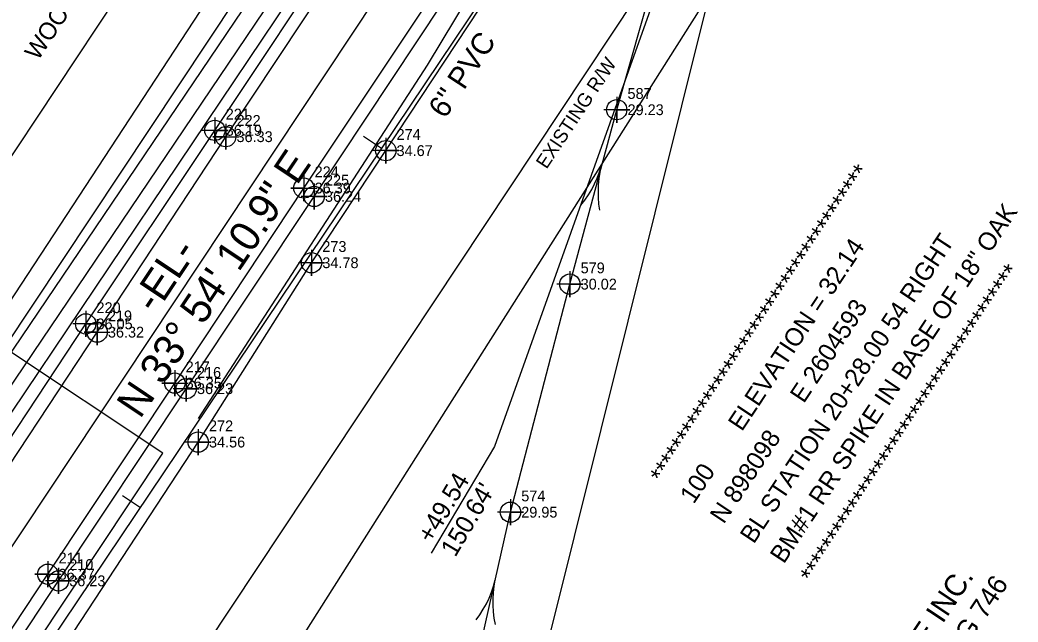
# Model space of a CAD drawing. Extents: x 2603627 to 2605187, y 896619 to 899063.
# Drawn here: x 2604393.2 to 2604624, y 897913.7 to 898052.8 of the extents above; entities that cross this region are included whole.
import ezdxf

# ---------------------------------------------------------------- set-up
doc = ezdxf.new("R2010")
doc.units = 0
for name, color, linetype in [('CTL Sheet Text', 7, 'Continuous'), ('Exist DTM Drainline Cogo Elevation', 7, 'Continuous'), ('Exist DTM Drainline Cogo Number', 7, 'Continuous'), ('Exist DTM Drainline Cogo Point CELL', 7, 'Continuous'), ('Exist Guardrail', 7, 'Continuous'), ('Exist Horizontal Alignment', 7, 'Continuous'), ('Exist Horizontal Alignment Direction Label', 7, 'Continuous'), ('Exist Horizontal Baseline Alignment', 7, 'Continuous'), ('Exist Horizontal Baseline Alignment Direction Label', 7, 'Continuous'), ('Exist Horizontal Baseline Alignment Tick small', 7, 'Continuous'), ('Exist Hydro Jurisdictional Stream or Body of Water', 7, 'Continuous'), ('Exist Hydro Stream Flow Arrow CELL', 7, 'Continuous'), ('Exist Property Deed Book Text', 7, 'Continuous'), ('Exist Property Line', 7, 'Continuous'), ('Exist Property Owner Text', 7, 'Continuous'), ('Exist Property Tie Line Leader', 7, 'Continuous'), ('Exist Property Tie Line Text', 7, 'Continuous'), ('Exist Right of Way Line', 7, 'Continuous'), ('Exist Right of Way Line Text', 7, 'Continuous'), ('Exist Roads EOP', 7, 'Continuous'), ('Exist Roads EOP Cogo Elevation', 7, 'Continuous'), ('Exist Roads EOP Cogo Number', 7, 'Continuous'), ('Exist Roads EOP Cogo Point CELL', 7, 'Continuous'), ('Exist Roads EOT', 7, 'Continuous'), ('Exist Roads EOT Cogo Elevation', 7, 'Continuous'), ('Exist Roads EOT Cogo Number', 7, 'Continuous'), ('Exist Roads EOT Cogo Point CELL', 7, 'Continuous'), ('Exist Utilities Telephone UG Cable SUE LOS C', 7, 'Continuous'), ('Exist Utilities Telephone UG FO SUE LOS C', 7, 'Continuous'), ('Exist Utilities Water UG Line SUE LOS B', 7, 'Continuous'), ('Exist Utilities Water UG Line SUE LOS B Cogo Elevation', 7, 'Continuous'), ('Exist Utilities Water UG Line SUE LOS B Cogo Number', 7, 'Continuous'), ('Exist Utilities Water UG Line SUE LOS B Cogo Point CELL', 7, 'Continuous'), ('Exist Utilities Water UG Line SUE LOS B Text', 7, 'Continuous'), ('Exist Vegetation Woods Line', 7, 'Continuous'), ('Exist Vegetation Woods Line Text', 7, 'Continuous')]:
    doc.layers.add(name, color=color, linetype=linetype)

# ---------------------------------------------------------------- blocks, each defined once
blk = doc.blocks.new('EXIST ROADS EOP COGO POINT')
at = {"layer": 'Exist Roads EOP Cogo Point CELL'}
blk.add_lwpolyline([(0, 0.06), (0, -0.06), (0, 0), (0.06, 0), (-0.06, 0)], dxfattribs=at)
blk.add_circle((0, 0), 0.0469, dxfattribs=at)
blk = doc.blocks.new('EXIST ROADS EOT COGO POINT')
at = {"layer": 'Exist Roads EOT Cogo Point CELL'}
blk.add_lwpolyline([(0, 0.06), (0, -0.06), (0, 0), (-0.06, 0), (0.06, 0)], dxfattribs=at)
blk.add_circle((0, 0), 0.0469, dxfattribs=at)
blk = doc.blocks.new('EXIST UTILITIES WATER UG LINE SUE LOS B COGO POINT')
at = {"layer": 'Exist Utilities Water UG Line SUE LOS B Cogo Point CELL'}
blk.add_lwpolyline([(0, 0.06), (0, -0.06), (0, 0), (0.06, 0), (-0.06, 0)], dxfattribs=at)
blk.add_circle((0, 0), 0.0469, dxfattribs=at)
blk = doc.blocks.new('EXIST DTM DRAINLINE COGO POINT')
at = {"layer": 'Exist DTM Drainline Cogo Point CELL'}
blk.add_lwpolyline([(0, 0.06), (0, -0.06), (0, 0), (0.06, 0), (-0.06, 0)], dxfattribs=at)
blk.add_circle((0, 0), 0.0469, dxfattribs=at)

msp = doc.modelspace()

# ---------------------------------------------------------------- linework, layer by layer
at = {"layer": 'Exist Guardrail'}
msp.add_lwpolyline([(2604516.08, 898089.95), (2604487.4, 898042.34), (2604434.45, 897960.66)], dxfattribs=at)
at = {"layer": 'Exist Horizontal Alignment'}
msp.add_line((2604046.33, 897411.6), (2604501.12, 898096.36), dxfattribs=at)
at = {"layer": 'Exist Horizontal Baseline Alignment'}
msp.add_line((2604301.74, 897762.53), (2604544.96, 898124.44), dxfattribs=at)
at = {"layer": 'Exist Horizontal Baseline Alignment Tick small'}
for p, q in [((2604476.83, 898023.06), (2604472.68, 898025.85)), ((2604421.06, 897940.07), (2604416.91, 897942.85))]:
    msp.add_line(p, q, dxfattribs=at)
at = {"layer": 'Exist Hydro Jurisdictional Stream or Body of Water'}
msp.add_lwpolyline([(2604496.63, 897894.57), (2604506.62, 897939.05), (2604520.36, 897991.75), (2604531.2, 898032.05), (2604542.79, 898072.73), (2604553.75, 898102.57), (2604562.26, 898124.95)], dxfattribs=at)
at = {"layer": 'Exist Hydro Stream Flow Arrow CELL'}
for p, q in [((2604526.4, 898014.23), (2604526.4, 898014.23)), ((2604502.01, 897918.51), (2604502.01, 897918.51))]:
    msp.add_line(p, q, dxfattribs=at)
for points in [[(2604522.9, 898009.99), (2604523.82, 898011.13), (2604524.64, 898012.39), (2604525.43, 898013.64), (2604526.1, 898014.92), (2604526.71, 898016.27), (2604527.25, 898017.66), (2604527.7, 898019.06)], [(2604527.31, 898008.81), (2604527.08, 898010.25), (2604527.01, 898011.75), (2604526.95, 898013.23), (2604527.02, 898014.67), (2604527.17, 898016.15), (2604527.4, 898017.62), (2604527.7, 898019.06)], [(2604498.68, 897914.14), (2604499.56, 897915.31), (2604500.32, 897916.6), (2604501.06, 897917.88), (2604501.68, 897919.19), (2604502.23, 897920.57), (2604502.71, 897921.98), (2604503.11, 897923.39)], [(2604503.15, 897913.13), (2604502.85, 897914.57), (2604502.72, 897916.06), (2604502.6, 897917.54), (2604502.6, 897918.98), (2604502.69, 897920.46), (2604502.86, 897921.95), (2604503.11, 897923.39)]]:
    msp.add_lwpolyline(points, dxfattribs=at)
at = {"layer": 'Exist Property Line'}
msp.add_line((2604562.45, 898098.35), (2604410.23, 897487.88), dxfattribs=at)
at = {"layer": 'Exist Property Tie Line Leader'}
msp.add_lwpolyline([(2604573.79, 898143.82), (2604569.62, 898141.11), (2604502.96, 897954.22), (2604488.28, 897929.59)], dxfattribs=at)
at = {"layer": 'Exist Right of Way Line'}
for p, q in [((2604004.68, 897439.26), (2604459.47, 898124.02)), ((2604087.98, 897383.94), (2604542.77, 898068.69))]:
    msp.add_line(p, q, dxfattribs=at)
at = {"layer": 'Exist Roads EOP'}
for points in [[(2604034.94, 897419.16), (2604054.97, 897449.51), (2604085.58, 897495.18), (2604114.88, 897539.87), (2604143.93, 897583.57), (2604172.72, 897627.19), (2604201.64, 897670.62), (2604230.5, 897714.45), (2604261.1, 897760.21), (2604291.23, 897805.76), (2604320.82, 897850.24), (2604350.34, 897894.81), (2604379.01, 897938.02), (2604408.4, 897982.56), (2604438.29, 898027.28), (2604468.22, 898072.28), (2604496.92, 898115.7)], [(2604057.72, 897404.05), (2604078.22, 897434.83), (2604108.36, 897480.05), (2604137.93, 897524.86), (2604167.35, 897568.96), (2604196.06, 897612.17), (2604224.86, 897655.68), (2604253.51, 897698.95), (2604283.96, 897744.64), (2604314.74, 897791.03), (2604343.97, 897835.34), (2604373.31, 897879.6), (2604402.1, 897923.18), (2604431.64, 897967.59), (2604461.24, 898012.02), (2604491.05, 898056.88), (2604519.7, 898100.47)]]:
    msp.add_lwpolyline(points, dxfattribs=at)
at = {"layer": 'Exist Roads EOT'}
for points in [[(2604037.37, 897417.54), (2604057.46, 897447.93), (2604087.91, 897493.66), (2604117.35, 897538.28), (2604146.54, 897581.98), (2604175.28, 897625.51), (2604204.1, 897668.97), (2604233.05, 897712.63), (2604263.81, 897758.51), (2604293.89, 897804.07), (2604323.3, 897848.54), (2604352.86, 897893.08), (2604381.65, 897936.11), (2604411.04, 897980.65), (2604440.78, 898025.82), (2604470.61, 898070.74), (2604499.36, 898114.11)], [(2604055.13, 897405.77), (2604075.39, 897436.3), (2604105.72, 897481.84), (2604135.41, 897526.58), (2604164.51, 897570.47), (2604193.14, 897613.84), (2604222.02, 897657.58), (2604250.73, 897700.63), (2604281.08, 897746.07), (2604311.9, 897792.56), (2604341.37, 897836.94), (2604370.82, 897881.24), (2604399.64, 897924.71), (2604429.03, 897968.88), (2604458.85, 898013.95), (2604488.44, 898058.33), (2604517.14, 898101.52)]]:
    msp.add_lwpolyline(points, dxfattribs=at)
at = {"layer": 'Exist Utilities Telephone UG Cable SUE LOS C'}
for p, q in [((2604364.02, 897921.59), (2604492.57, 898112.76)), ((2604389.62, 897977.06), (2604474.1, 898104.18)), ((2604426.24, 897952.72), (2604389.62, 897977.06)), ((2604201.56, 897614.6), (2604426.24, 897952.72))]:
    msp.add_line(p, q, dxfattribs=at)
at = {"layer": 'Exist Utilities Telephone UG FO SUE LOS C'}
for p, q in [((2604020.98, 897428.41), (2604461.82, 898080.46)), ((2604024.53, 897426.06), (2604465.37, 898078.1))]:
    msp.add_line(p, q, dxfattribs=at)
at = {"layer": 'Exist Utilities Water UG Line SUE LOS B'}
msp.add_lwpolyline([(2604076.5, 897391.6), (2604089.19, 897412.44), (2604108.02, 897444.81), (2604130.46, 897486.17), (2604138.61, 897502.5), (2604141.74, 897510.42), (2604157.29, 897542.11), (2604195.61, 897598.86), (2604232.99, 897655.2), (2604269.72, 897709.19), (2604303.43, 897758.71), (2604343.24, 897819.02), (2604371.6, 897861.28), (2604402.52, 897906.63), (2604434.42, 897955.25), (2604460.63, 897996.69), (2604477.79, 898022.59), (2604502.25, 898059.64), (2604529.4, 898098.89), (2604530.47, 898100.43), (2604537.02, 898109.88), (2604550.55, 898129.28)], dxfattribs=at)
at = {"layer": 'Exist Vegetation Woods Line'}
for points in [[(2604476.15, 898117.83), (2604185.5, 897674.67)], [(2604278.2, 897626.01), (2604559.06, 898068.86)]]:
    msp.add_lwpolyline(points, dxfattribs=at)

# ---------------------------------------------------------------- block references
at = {"layer": 'Exist DTM Drainline Cogo Point CELL', "xscale": 50, "yscale": 50}
for p in [(2604531.2, 898032.05), (2604520.36, 897991.75), (2604506.62, 897939.05)]:
    msp.add_blockref('EXIST DTM DRAINLINE COGO POINT', p, dxfattribs=at)
at = {"layer": 'Exist Roads EOP Cogo Point CELL', "xscale": 50, "yscale": 50}
for p in [(2604438.29, 898027.28), (2604461.24, 898012.02), (2604408.4, 897982.56), (2604431.64, 897967.59), (2604402.1, 897923.18)]:
    msp.add_blockref('EXIST ROADS EOP COGO POINT', p, dxfattribs=at)
at = {"layer": 'Exist Roads EOT Cogo Point CELL', "xscale": 50, "yscale": 50}
for p in [(2604440.78, 898025.82), (2604458.85, 898013.95), (2604411.04, 897980.65), (2604429.03, 897968.88), (2604399.64, 897924.71)]:
    msp.add_blockref('EXIST ROADS EOT COGO POINT', p, dxfattribs=at)
at = {"layer": 'Exist Utilities Water UG Line SUE LOS B Cogo Point CELL', "xscale": 50, "yscale": 50}
for p in [(2604477.79, 898022.59), (2604460.63, 897996.69), (2604434.42, 897955.25)]:
    msp.add_blockref('EXIST UTILITIES WATER UG LINE SUE LOS B COGO POINT', p, dxfattribs=at)

# ---------------------------------------------------------------- texts
at = {"layer": 'CTL Sheet Text'}
for s, p in [('****************************************', (2604542.07, 897945.37)), ('BM#1 RR SPIKE IN BASE OF 18" OAK', (2604569.84, 897926.93)), ('BL STATION 20+28.00 54 RIGHT', (2604562.89, 897931.54)), ('100       ELEVATION = 32.14', (2604549.01, 897940.76)), ('****************************************', (2604576.78, 897922.32)), ('N 898098      E 2604593', (2604555.95, 897936.15))]:
    msp.add_text(s, height=4.1667, rotation=56.4094, dxfattribs=at).set_placement(p)
at = {"layer": 'Exist DTM Drainline Cogo Elevation'}
for s, p in [('29.23', (2604533.7, 898030.8)), ('30.02', (2604522.86, 897990.5)), ('29.95', (2604509.12, 897937.8))]:
    msp.add_text(s, height=2.5, dxfattribs=at).set_placement(p)
at = {"layer": 'Exist DTM Drainline Cogo Number'}
for s, p in [('587', (2604533.7, 898034.55)), ('579', (2604522.86, 897994.25)), ('574', (2604509.12, 897941.55))]:
    msp.add_text(s, height=2.5, dxfattribs=at).set_placement(p)
at = {"layer": 'Exist Horizontal Alignment Direction Label'}
msp.add_text('-EL-', height=7, rotation=56.4094, dxfattribs=at).set_placement((2604424.55, 897984.67))
at = {"layer": 'Exist Horizontal Baseline Alignment Direction Label'}
msp.add_text('N 33%%d 54\' 10.9" E', height=7, rotation=56.097, dxfattribs=at).set_placement((2604420.97, 897960.41))
at = {"layer": 'Exist Property Deed Book Text'}
msp.add_text('DB 642 PG 746', height=4.5, rotation=56.4133, dxfattribs=at).set_placement((2604598.6, 897887.36))
at = {"layer": 'Exist Property Owner Text'}
msp.add_text('ELE INC.', height=5, rotation=56.4133, dxfattribs=at).set_placement((2604598.54, 897901.04))
at = {"layer": 'Exist Property Tie Line Text'}
for s, p in [('+49.54', (2604488.41, 897931.64)), ("150.64'", (2604493.86, 897928.47))]:
    msp.add_text(s, height=4.2, rotation=59.1717, dxfattribs=at).set_placement(p)
at = {"layer": 'Exist Right of Way Line Text'}
msp.add_text('EXISTING R/W', height=3.2, rotation=56.4094, dxfattribs=at).set_placement((2604514.97, 898018.17))
at = {"layer": 'Exist Roads EOP Cogo Elevation'}
for s, p in [('36.19', (2604440.79, 898026.03)), ('36.24', (2604463.74, 898010.77)), ('36.05', (2604410.9, 897981.31)), ('36.23', (2604434.14, 897966.34)), ('36.23', (2604404.6, 897921.93))]:
    msp.add_text(s, height=2.5, dxfattribs=at).set_placement(p)
at = {"layer": 'Exist Roads EOP Cogo Number'}
for s, p in [('221', (2604440.79, 898029.78)), ('225', (2604463.74, 898014.52)), ('220', (2604410.9, 897985.06)), ('216', (2604434.14, 897970.09)), ('210', (2604404.6, 897925.68))]:
    msp.add_text(s, height=2.5, dxfattribs=at).set_placement(p)
at = {"layer": 'Exist Roads EOT Cogo Elevation'}
for s, p in [('36.33', (2604443.28, 898024.57)), ('36.39', (2604461.35, 898012.7)), ('36.32', (2604413.54, 897979.4)), ('36.35', (2604431.53, 897967.63)), ('36.37', (2604402.14, 897923.46))]:
    msp.add_text(s, height=2.5, dxfattribs=at).set_placement(p)
at = {"layer": 'Exist Roads EOT Cogo Number'}
for s, p in [('222', (2604443.28, 898028.32)), ('224', (2604461.35, 898016.45)), ('219', (2604413.54, 897983.15)), ('217', (2604431.53, 897971.38)), ('211', (2604402.14, 897927.21))]:
    msp.add_text(s, height=2.5, dxfattribs=at).set_placement(p)
at = {"layer": 'Exist Utilities Water UG Line SUE LOS B Cogo Elevation'}
for s, p in [('34.67', (2604480.29, 898021.34)), ('34.78', (2604463.13, 897995.44)), ('34.56', (2604436.92, 897954))]:
    msp.add_text(s, height=2.5, dxfattribs=at).set_placement(p)
at = {"layer": 'Exist Utilities Water UG Line SUE LOS B Cogo Number'}
for s, p in [('274', (2604480.29, 898025.09)), ('273', (2604463.13, 897999.19)), ('272', (2604436.92, 897957.75))]:
    msp.add_text(s, height=2.5, dxfattribs=at).set_placement(p)
at = {"layer": 'Exist Utilities Water UG Line SUE LOS B Text'}
msp.add_text('6" PVC', height=5, rotation=56.5594, dxfattribs=at).set_placement((2604491.51, 898029.77))
at = {"layer": 'Exist Vegetation Woods Line Text'}
msp.add_text('WOODS', height=4, rotation=56.4094, dxfattribs=at).set_placement((2604397.38, 898043.22))

doc.saveas('drawing.dxf')
